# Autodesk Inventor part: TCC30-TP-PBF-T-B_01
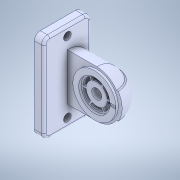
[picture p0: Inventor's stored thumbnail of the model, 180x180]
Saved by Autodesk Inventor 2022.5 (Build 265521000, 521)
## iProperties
Created: 2023-09
Part Number: TCC30-TP-PBF-T-B_01
Material: 一般
Document SubType Name: Modeling
Designer: ImaoCorp
Density: 1 g/cm^3
Appearance: 既定
Author: ImaoCorp
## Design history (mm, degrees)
feature "TCC30-TP-PBF-T-B_01"
node "ソリッド1"
